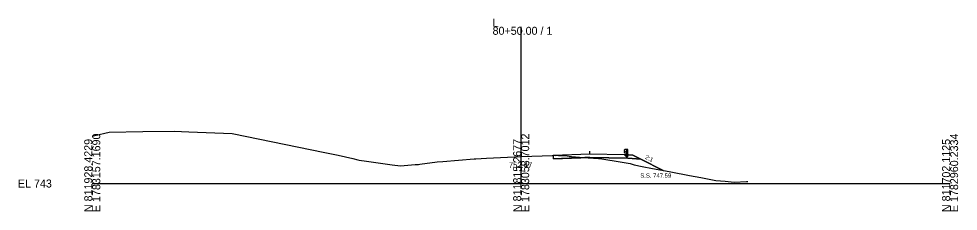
# Model space of a CAD drawing. Extents: x -26 to 7903, y -10 to 9573.
# Drawn here: x 4974.3 to 5302.8, y 1490.3 to 1557.7 of the extents above; entities that cross this region are included whole.
import ezdxf

# ---------------------------------------------------------------- set-up
doc = ezdxf.new("R2010")
doc.units = 0
for name, color, linetype in [('Exist Cross Section Cell', 7, 'Continuous'), ('Exist XS Center Line Elevation Label', 7, 'Continuous'), ('Exist XS Ground Line', 7, 'Continuous'), ('Prop XS Dump Level', 7, 'Continuous'), ('Prop XS Earthwork Shape', 7, 'Continuous'), ('Prop XS EOT Tick Mark', 7, 'Continuous'), ('Prop XS Finish Grade', 7, 'Continuous'), ('Prop XS Finish Grade Earthwork', 7, 'Continuous'), ('Prop XS Finish Grade Paved Shoulder', 7, 'Continuous'), ('Prop XS Finish Grade Pavement', 7, 'Continuous'), ('Prop XS Guardrail', 7, 'Continuous'), ('Prop XS Pvmt Edge Slope', 7, 'Continuous'), ('Prop XS Side Slope Text', 7, 'Continuous'), ('Prop XS SS Elevation Text', 7, 'Continuous'), ('Prop XS Subgrade Earthwork', 7, 'Continuous'), ('Scratch_Level_3', 7, 'Continuous'), ('Scratch_Level_6', 7, 'Continuous')]:
    doc.layers.add(name, color=color, linetype=linetype)

msp = doc.modelspace()

# ---------------------------------------------------------------- linework, layer by layer
at = {"layer": 'Exist Cross Section Cell'}
for p, q in [((5150, 1500), (5150, 1554.85)), ((5000, 1500), (5150, 1500)), ((5150, 1500), (5300, 1500))]:
    msp.add_line(p, q, dxfattribs=at)
at = {"layer": 'Exist XS Ground Line'}
for p, q in [((5000.93, 1516.82), (5005.88, 1518.03)), ((5005.88, 1518.03), (5017.66, 1518.26)), ((5017.66, 1518.26), (5028.6, 1518.28)), ((5028.6, 1518.28), (5033.77, 1518.12)), ((5033.77, 1518.12), (5048.97, 1517.56)), ((5000, 1516.6), (5000.93, 1516.82)), ((5048.97, 1517.56), (5081.31, 1510.91)), ((5081.31, 1510.91), (5085.97, 1509.98)), ((5085.97, 1509.98), (5091.14, 1508.76)), ((5091.14, 1508.76), (5092.82, 1508.33)), ((5092.82, 1508.33), (5093.38, 1508.21)), ((5093.38, 1508.21), (5094.15, 1508.11)), ((5094.15, 1508.11), (5095.06, 1507.99)), ((5095.06, 1507.99), (5104.92, 1506.57)), ((5122.58, 1507.67), (5133.59, 1508.61)), ((5133.59, 1508.61), (5134.16, 1508.66)), ((5134.16, 1508.66), (5137.89, 1508.87)), ((5137.89, 1508.87), (5150.08, 1509.47)), ((5150.08, 1509.47), (5160.94, 1509.86)), ((5160.94, 1509.86), (5161.35, 1509.88)), ((5161.35, 1509.88), (5163.06, 1509.84)), ((5163.06, 1509.84), (5165.3, 1509.78)), ((5165.3, 1509.78), (5167.63, 1509.51)), ((5167.63, 1509.51), (5170.39, 1509.24)), ((5170.39, 1509.24), (5171.68, 1509.08)), ((5171.68, 1509.08), (5177.05, 1508.77)), ((5177.05, 1508.77), (5178.16, 1508.68)), ((5178.16, 1508.68), (5178.96, 1508.58)), ((5178.96, 1508.58), (5183.96, 1507.68)), ((5104.92, 1506.57), (5107.81, 1506.17)), ((5107.81, 1506.17), (5112.98, 1506.62)), ((5112.98, 1506.62), (5114.12, 1506.71)), ((5114.12, 1506.71), (5114.55, 1506.78)), ((5114.55, 1506.78), (5120.6, 1507.54)), ((5120.6, 1507.54), (5122.58, 1507.67)), ((5183.96, 1507.68), (5188.1, 1506.95)), ((5188.1, 1506.95), (5189.52, 1506.57)), ((5189.52, 1506.57), (5192.32, 1505.94)), ((5192.32, 1505.94), (5195.96, 1505.2)), ((5195.96, 1505.2), (5199.17, 1504.66)), ((5199.17, 1504.66), (5202.3, 1504.13)), ((5202.3, 1504.13), (5208.86, 1502.82)), ((5208.86, 1502.82), (5212.82, 1502.08)), ((5212.82, 1502.08), (5218.02, 1501.11)), ((5218.02, 1501.11), (5221.36, 1500.81)), ((5221.36, 1500.81), (5224.46, 1500.53)), ((5224.46, 1500.53), (5228.81, 1500.72)), ((5228.81, 1500.72), (5229.31, 1500.69))]:
    msp.add_line(p, q, dxfattribs=at)
at = {"layer": 'Prop XS Dump Level'}
msp.add_line((5161.32, 1509.92), (5174, 1510.43), dxfattribs=at)
at = {"layer": 'Prop XS Earthwork Shape'}
for points in [[(5165.3, 1509.78), (5167.63, 1509.51), (5170.39, 1509.24), (5171.68, 1509.08), (5172.24, 1509.05), (5161.35, 1508.63), (5161.35, 1509.88), (5163.06, 1509.84)], [(5172.24, 1509.05), (5177.05, 1508.77), (5178.16, 1508.68), (5178.96, 1508.58), (5183.96, 1507.68), (5188.1, 1506.95), (5189.52, 1506.57), (5192.32, 1505.94), (5195.96, 1505.2), (5199.17, 1504.66), (5199.6, 1504.59), (5191.79, 1508.49), (5187.28, 1508.85), (5174.01, 1509.12)]]:
    msp.add_lwpolyline(points, close=True, dxfattribs=at)
at = {"layer": 'Prop XS EOT Tick Mark'}
msp.add_line((5174, 1510.37), (5174, 1511.37), dxfattribs=at)
at = {"layer": 'Prop XS Finish Grade'}
for p, q in [((5186, 1510.13), (5189, 1509.89)), ((5189, 1509.89), (5191.79, 1508.49))]:
    msp.add_line(p, q, dxfattribs=at)
at = {"layer": 'Prop XS Finish Grade Earthwork'}
msp.add_line((5191.79, 1508.49), (5199.6, 1504.59), dxfattribs=at)
at = {"layer": 'Prop XS Finish Grade Paved Shoulder'}
msp.add_line((5174, 1510.37), (5186, 1510.13), dxfattribs=at)
at = {"layer": 'Prop XS Finish Grade Pavement'}
msp.add_line((5161.35, 1509.88), (5174, 1510.37), dxfattribs=at)
at = {"layer": 'Prop XS Guardrail'}
for p, q in [((5186.03, 1511.66), (5186, 1511.6)), ((5186, 1511.6), (5186.03, 1511.54)), ((5186.32, 1511.86), (5186.03, 1511.66)), ((5186.03, 1511.54), (5186.32, 1511.34)), ((5186.82, 1511.86), (5186.32, 1511.86)), ((5186.32, 1511.34), (5186.32, 1511.24)), ((5187.32, 1511.86), (5186.82, 1511.86)), ((5186.82, 1511.86), (5186.82, 1509.36)), ((5187.32, 1509.36), (5187.32, 1511.86)), ((5186.03, 1511.04), (5186, 1510.98)), ((5186, 1510.98), (5186.03, 1510.92)), ((5186.32, 1511.24), (5186.03, 1511.04)), ((5186.03, 1510.92), (5186.32, 1510.72)), ((5186.32, 1510.72), (5186.82, 1510.72))]:
    msp.add_line(p, q, dxfattribs=at)
at = {"layer": 'Prop XS Pvmt Edge Slope'}
msp.add_line((5186, 1510.13), (5187.28, 1508.85), dxfattribs=at)
at = {"layer": 'Prop XS Subgrade Earthwork'}
for p, q in [((5161.35, 1508.63), (5161.35, 1509.88)), ((5161.35, 1508.63), (5174.01, 1509.12)), ((5174.01, 1509.12), (5187.28, 1508.85)), ((5187.28, 1508.85), (5191.79, 1508.49))]:
    msp.add_line(p, q, dxfattribs=at)
at = {"layer": 'Scratch_Level_3'}
for p, q in [((5189, 1509.89), (5186, 1510.13)), ((5186, 1510.13), (5187.28, 1508.85)), ((5187.28, 1508.85), (5191.79, 1508.49)), ((5191.79, 1508.49), (5189, 1509.89))]:
    msp.add_line(p, q, dxfattribs=at)
at = {"layer": 'Scratch_Level_6'}
msp.add_lwpolyline([(5163.06, 1509.84), (5165.3, 1509.78), (5167.63, 1509.51), (5170.39, 1509.24), (5171.68, 1509.08), (5172.24, 1509.05), (5161.35, 1508.63), (5161.35, 1509.88)], close=True, dxfattribs=at)

# ---------------------------------------------------------------- texts
at = {"layer": 'Exist Cross Section Cell'}
for s, p in [('L', (5140, 1554.85)), ('80+50.00 / 1', (5140, 1552.05)), ('EL 743', (4974, 1498.6))]:
    msp.add_text(s, height=2.8, dxfattribs=at).set_placement(p)
for s, p in [('N 811928.4229', (5000, 1490)), ('E 1783157.1690', (5002.8, 1490)), ('N 811815.2677', (5150, 1490)), ('E 1783058.7012', (5152.8, 1490)), ('N 811702.1125', (5300, 1490)), ('E 1782960.2334', (5302.8, 1490))]:
    msp.add_text(s, height=2.8, rotation=90, dxfattribs=at).set_placement(p)
at = {"layer": 'Exist XS Center Line Elevation Label'}
msp.add_text('752.47', height=2, dxfattribs=at).set_placement((5145.7, 1505.47))
at = {"layer": 'Prop XS Dump Level'}
for s, height, p in [('Eop', 0.3, (5161.35, 1509.58)), ('Case4', 0.04, (5186, 1509.61))]:
    msp.add_text(s, height=height, dxfattribs=at).set_placement(p)
at = {"layer": 'Prop XS Side Slope Text'}
msp.add_text('2:1', height=1.5, rotation=333.4349, dxfattribs=at).set_placement((5193.17, 1508.74))
at = {"layer": 'Prop XS SS Elevation Text'}
msp.add_text('S.S. 747.59', height=1.5, dxfattribs=at).set_placement((5191.67, 1502.04))

doc.saveas('drawing.dxf')
